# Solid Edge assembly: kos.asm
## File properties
Author: Cymax
Template: Normal.asm
Last saved by: haldur
Revision: 21
Application: Solid Edge
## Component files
pohi.par
kiil.par
pealis.par
kaiut.par
silt.psm
klaas.par
lipp.par
klaas_mir.par
klaas_mir1.par
klaas_mir2.par
mast.par
puri.par
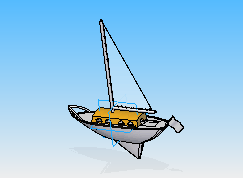
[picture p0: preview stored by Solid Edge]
